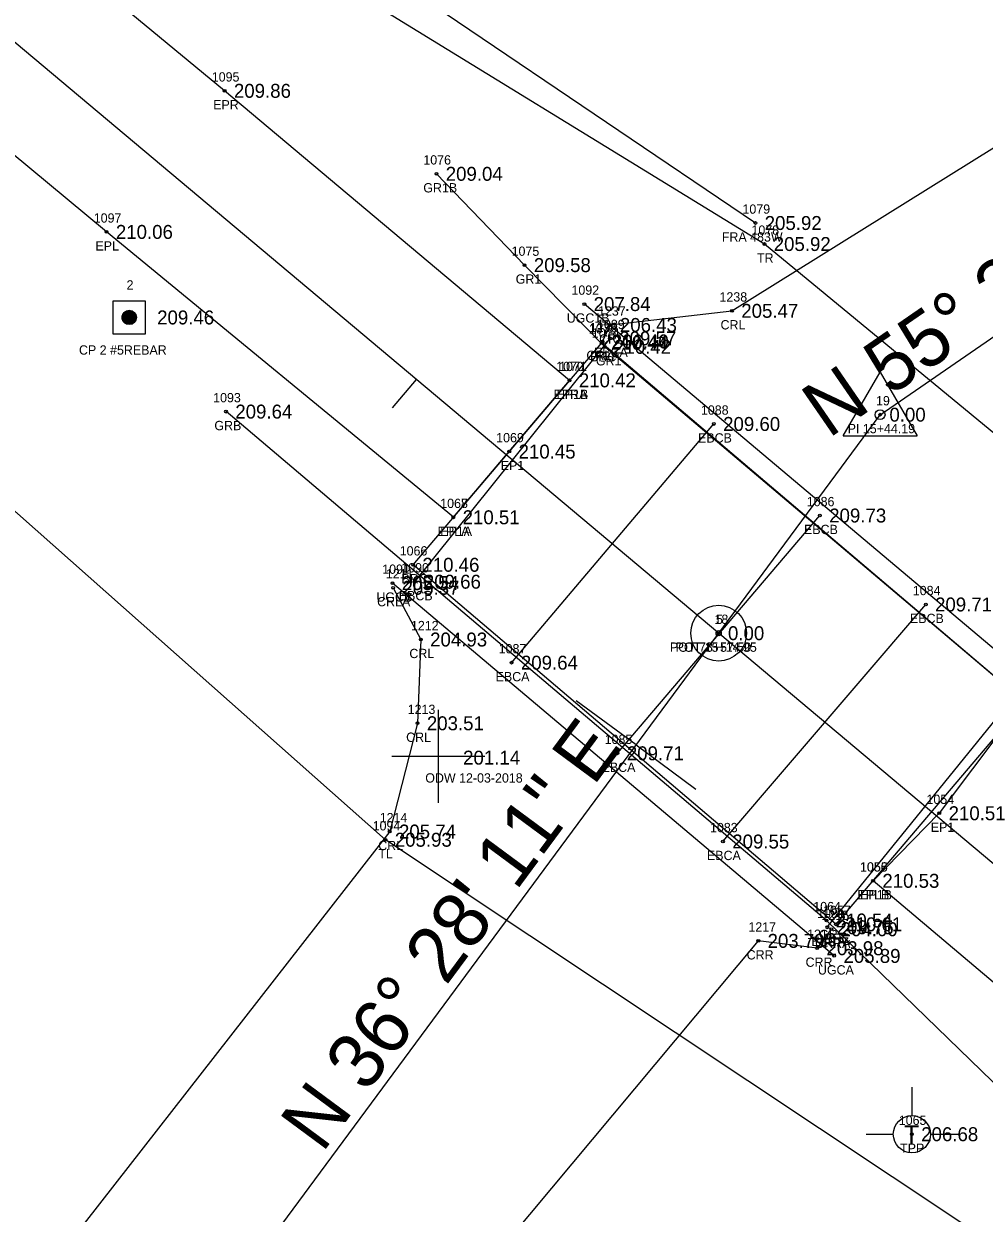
# Model space of a CAD drawing. Extents: x 2259948 to 2261336, y 1064647 to 1065986.
# Drawn here: x 2260727.2 to 2260830.6, y 1065022.5 to 1065150.5 of the extents above; entities that cross this region are included whole.
import ezdxf

# ---------------------------------------------------------------- set-up
doc = ezdxf.new("R2010")
doc.units = 0
for name, color, linetype in [('RD_EX_Bridge', 7, 'Continuous'), ('RD_EX_Bridge_txCode', 7, 'Continuous'), ('RD_EX_Fence_Other', 7, 'Continuous'), ('RD_EX_Fence_Other_txCode', 7, 'Continuous'), ('RD_EX_GuardRail', 7, 'Continuous'), ('RD_EX_GuardRail_txCode', 7, 'Continuous'), ('RD_EX_H2O', 7, 'Continuous'), ('RD_EX_H2O_txCode', 7, 'Continuous'), ('RD_EX_Road', 7, 'Continuous'), ('RD_EX_Road_txCode', 7, 'Continuous'), ('RD_EX_TX_Bridge_ELEV', 7, 'Continuous'), ('RD_EX_TX_Fence_Other_ELEV', 7, 'Continuous'), ('RD_EX_TX_GuardRail_ELEV', 7, 'Continuous'), ('RD_EX_TX_H2O_ELEV', 7, 'Continuous'), ('RD_EX_TX_Road_ELEV', 7, 'Continuous'), ('RD_EX_TX_UT_ELEV', 7, 'Continuous'), ('RD_EX_TX_VEG_ELEV', 7, 'Continuous'), ('RD_EX_UT', 7, 'Continuous'), ('RD_EX_UT_txCode', 7, 'Continuous'), ('RD_EX_VEG', 7, 'Continuous'), ('RD_EX_VEG_txCode', 7, 'Continuous'), ('RD_HC_Cl', 7, 'Continuous'), ('RD_HC_Data', 7, 'Continuous'), ('RD_HC_Data_Tic', 7, 'Continuous'), ('RD_HC_Survey', 7, 'Continuous'), ('RD_HC_Survey_ELEV', 7, 'Continuous'), ('RD_HC_Survey_txCode', 7, 'Continuous'), ('RD_HC_txCode', 7, 'Continuous'), ('RD_SMD_Locator', 7, 'Continuous')]:
    doc.layers.add(name, color=color, linetype=linetype)

msp = doc.modelspace()

# ---------------------------------------------------------------- linework, layer by layer
at = {"layer": 'RD_EX_Bridge'}
for p, q in [((2260790.29, 1065116.62), (2260769.27, 1065090.44)), ((2260779.71, 1065081.73), (2260801.47, 1065107.41)), ((2260791.11, 1065071.98), (2260812.88, 1065097.56)), ((2260802.45, 1065062.49), (2260824.27, 1065087.99)), ((2260813.68, 1065053.26), (2260834.73, 1065079.24))]:
    msp.add_line(p, q, dxfattribs=at)
msp.add_lwpolyline([(2260834.92, 1065077.53), (2260814.6, 1065053.58), (2260769.11, 1065092.26), (2260789.4, 1065116.14), (2260834.92, 1065077.53)], dxfattribs=at)
at = {"layer": 'RD_EX_Fence_Other'}
msp.add_lwpolyline([(2260805.94, 1065129.03), (2260757.87, 1065161.54), (2260648.62, 1065258.75)], dxfattribs=at)
at = {"layer": 'RD_EX_GuardRail'}
for points in [[(2260856.34, 1065064.4), (2260844.56, 1065071.16), (2260834.49, 1065077.85), (2260789.73, 1065115.71), (2260781.1, 1065124.5), (2260771.62, 1065134.32)], [(2260832.64, 1065035.52), (2260813.58, 1065053.99), (2260748.98, 1065108.74)]]:
    msp.add_lwpolyline(points, dxfattribs=at)
at = {"layer": 'RD_EX_H2O'}
for p, q in [((2260771.83, 1065066.66), (2260771.83, 1065076.66)), ((2260766.83, 1065071.66), (2260776.83, 1065071.66))]:
    msp.add_line(p, q, dxfattribs=at)
for points in [[(2260789.48, 1065116.29), (2260790.36, 1065118.06), (2260803.42, 1065119.58), (2260845.64, 1065145.91), (2260874.83, 1065172.21)], [(2260766.96, 1065089.79), (2260769.94, 1065084.22), (2260769.59, 1065075.21), (2260766.59, 1065063.56), (2260718.2, 1065001.51), (2260666.03, 1064928.94), (2260617.31, 1064851.47), (2260573.34, 1064761.94), (2260536.11, 1064718.88), (2260488.15, 1064682.39)], [(2260814.11, 1065053.05), (2260812.59, 1065051.01), (2260806.25, 1065051.8), (2260750.48, 1064985.06), (2260697.06, 1064907.27), (2260648.8, 1064826.07), (2260606.38, 1064743.85), (2260584.89, 1064714.82), (2260586.34, 1064702.25), (2260547.45, 1064661.75), (2260541.67, 1064664.24), (2260523.34, 1064649.3)]]:
    msp.add_lwpolyline(points, dxfattribs=at)
at = {"layer": 'RD_EX_Road'}
for points in [[(2260785.94, 1065112.1), (2260748.83, 1065143.25), (2260679.89, 1065200.15), (2260614.93, 1065253.84), (2260576.4, 1065286.6), (2260541.88, 1065316.4), (2260503.82, 1065350.69)], [(2260773.44, 1065097.37), (2260736.13, 1065128.07), (2260602.8, 1065238.77), (2260563.77, 1065270.54), (2260528.16, 1065301.97), (2260490.72, 1065336.18)], [(2260773.44, 1065097.37), (2260779.46, 1065104.44), (2260785.94, 1065112.1)], [(2260832.89, 1065075.07), (2260825.73, 1065065.53), (2260818.6, 1065058.26)], [(2261112.68, 1064810.86), (2261032.95, 1064877.72), (2260956.01, 1064942.53), (2260884.53, 1065002.6), (2260818.6, 1065058.26)]]:
    msp.add_lwpolyline(points, dxfattribs=at)
at = {"layer": 'RD_EX_UT'}
for p, q in [((2260837.52, 1065078.2), (2260787.54, 1065120.31)), ((2260814.42, 1065050.18), (2260766.89, 1065090.29)), ((2260822.78, 1065036.07), (2260822.78, 1065033)), ((2260817.85, 1065031.01), (2260820.78, 1065031.01)), ((2260824.78, 1065031.01), (2260827.85, 1065031.01))]:
    msp.add_line(p, q, dxfattribs=at)
msp.add_circle((2260822.78, 1065031), 2, dxfattribs=at)
at = {"layer": 'RD_EX_VEG'}
for points in [[(2261134.31, 1064842.95), (2260842.2, 1065097.67), (2260806.91, 1065126.77), (2260758.4, 1065156.57), (2260401.57, 1065481.47), (2260414.95, 1065532.7)], [(2261105.29, 1064796.67), (2260883, 1064984.96), (2260766.14, 1065062.68), (2260367.33, 1065416.28), (2260257.33, 1065527.76)]]:
    msp.add_lwpolyline(points, dxfattribs=at)
at = {"layer": 'RD_HC_Cl'}
for p, q in [((2261118.79, 1064819.11), (2260589.55, 1065263.13)), ((2260819.36, 1065108.41), (2260855.45, 1065133.27)), ((2260734.19, 1064993.17), (2260819.36, 1065108.41))]:
    msp.add_line(p, q, dxfattribs=at)
at = {"layer": 'RD_HC_Data'}
for p, q in [((2260815.39, 1065106.12), (2260819.37, 1065113)), ((2260819.37, 1065113), (2260823.33, 1065106.12)), ((2260815.39, 1065106.12), (2260823.33, 1065106.12))]:
    msp.add_line(p, q, dxfattribs=at)
for centre, radius in [((2260819.36, 1065108.41), 0.529), ((2260801.99, 1065084.9), 3), ((2260801.99, 1065084.9), 3), ((2260801.99, 1065084.9), 0.282), ((2260801.99, 1065084.9), 0.282)]:
    msp.add_circle(centre, radius, dxfattribs=at)
at = {"layer": 'RD_HC_Data_Tic'}
for p, q in [((2260769.43, 1065112.21), (2260766.86, 1065109.15)), ((2260793.1, 1065072.88), (2260786.67, 1065077.63)), ((2260793.1, 1065072.88), (2260799.53, 1065068.12))]:
    msp.add_line(p, q, dxfattribs=at)
at = {"layer": 'RD_HC_Survey'}
for p, q in [((2260737.84, 1065118.6), (2260737.84, 1065119.13)), ((2260737.87, 1065118.54), (2260737.87, 1065119.19)), ((2260737.89, 1065118.49), (2260737.89, 1065119.24)), ((2260737.92, 1065118.45), (2260737.92, 1065119.28)), ((2260737.94, 1065118.42), (2260737.94, 1065119.31)), ((2260737.97, 1065118.38), (2260737.97, 1065119.35)), ((2260737.99, 1065118.35), (2260737.99, 1065119.38)), ((2260738.02, 1065118.33), (2260738.02, 1065119.4)), ((2260738.04, 1065118.3), (2260738.04, 1065119.43)), ((2260738.07, 1065118.28), (2260738.07, 1065119.45)), ((2260738.09, 1065118.26), (2260738.09, 1065119.47)), ((2260738.11, 1065118.24), (2260738.11, 1065119.49)), ((2260738.14, 1065118.22), (2260738.14, 1065119.51)), ((2260738.16, 1065118.21), (2260738.16, 1065119.52)), ((2260738.19, 1065118.19), (2260738.19, 1065119.54)), ((2260738.21, 1065118.18), (2260738.21, 1065119.55)), ((2260738.24, 1065118.17), (2260738.24, 1065119.56)), ((2260738.26, 1065118.16), (2260738.26, 1065119.57)), ((2260738.29, 1065118.15), (2260738.29, 1065119.58)), ((2260738.31, 1065118.14), (2260738.31, 1065119.59)), ((2260738.34, 1065118.13), (2260738.34, 1065119.6)), ((2260738.36, 1065118.12), (2260738.36, 1065119.61)), ((2260738.39, 1065118.12), (2260738.39, 1065119.61)), ((2260738.41, 1065118.11), (2260738.41, 1065119.62)), ((2260738.44, 1065118.11), (2260738.44, 1065119.62)), ((2260738.46, 1065118.1), (2260738.46, 1065119.63)), ((2260738.49, 1065118.1), (2260738.49, 1065119.63)), ((2260738.51, 1065118.1), (2260738.51, 1065119.63)), ((2260738.54, 1065118.1), (2260738.54, 1065119.63)), ((2260738.56, 1065118.1), (2260738.56, 1065119.63)), ((2260738.59, 1065118.1), (2260738.59, 1065119.63)), ((2260738.61, 1065118.1), (2260738.61, 1065119.63)), ((2260738.63, 1065118.1), (2260738.63, 1065119.63)), ((2260738.66, 1065118.1), (2260738.66, 1065119.63)), ((2260738.68, 1065118.1), (2260738.68, 1065119.63)), ((2260738.71, 1065118.11), (2260738.71, 1065119.62)), ((2260738.73, 1065118.11), (2260738.73, 1065119.62)), ((2260738.76, 1065118.12), (2260738.76, 1065119.61)), ((2260738.78, 1065118.13), (2260738.78, 1065119.6)), ((2260738.81, 1065118.13), (2260738.81, 1065119.6)), ((2260738.83, 1065118.14), (2260738.83, 1065119.59)), ((2260738.86, 1065118.15), (2260738.86, 1065119.58)), ((2260738.88, 1065118.16), (2260738.88, 1065119.57)), ((2260738.91, 1065118.18), (2260738.91, 1065119.56)), ((2260738.93, 1065118.19), (2260738.93, 1065119.54)), ((2260738.96, 1065118.2), (2260738.96, 1065119.53)), ((2260738.98, 1065118.22), (2260738.98, 1065119.51)), ((2260739.01, 1065118.23), (2260739.01, 1065119.5)), ((2260739.03, 1065118.25), (2260739.03, 1065119.48)), ((2260739.06, 1065118.27), (2260739.06, 1065119.46)), ((2260739.08, 1065118.29), (2260739.08, 1065119.44)), ((2260739.1, 1065118.32), (2260739.1, 1065119.41)), ((2260739.13, 1065118.34), (2260739.13, 1065119.39)), ((2260739.15, 1065118.37), (2260739.15, 1065119.36)), ((2260739.18, 1065118.4), (2260739.18, 1065119.33)), ((2260739.2, 1065118.43), (2260739.2, 1065119.3)), ((2260739.23, 1065118.47), (2260739.23, 1065119.26)), ((2260739.25, 1065118.52), (2260739.25, 1065119.21)), ((2260739.28, 1065118.57), (2260739.28, 1065119.16)), ((2260739.3, 1065118.64), (2260739.3, 1065119.09)), ((2260737.82, 1065118.69), (2260737.82, 1065119.04)), ((2260739.33, 1065118.75), (2260739.33, 1065118.98))]:
    msp.add_line(p, q, dxfattribs=at)
msp.add_lwpolyline([(2260740.32, 1065120.62), (2260736.82, 1065120.62), (2260736.82, 1065117.12), (2260740.32, 1065117.12)], close=True, dxfattribs=at)
msp.add_circle((2260738.57, 1065118.87), 0.769, dxfattribs=at)
at = {"layer": 'RD_SMD_Locator'}
for centre in [(2260748.83, 1065143.25), (2260771.62, 1065134.32), (2260736.13, 1065128.07), (2260805.94, 1065129.03), (2260806.91, 1065126.77), (2260781.1, 1065124.5), (2260787.54, 1065120.31), (2260803.42, 1065119.58), (2260738.57, 1065118.87), (2260790.36, 1065118.06), (2260790.29, 1065116.62), (2260789.4, 1065116.14), (2260789.48, 1065116.29), (2260789.73, 1065115.71), (2260785.94, 1065112.1), (2260785.94, 1065112.1), (2260748.98, 1065108.74), (2260801.47, 1065107.41), (2260819.36, 1065108.41), (2260779.46, 1065104.44), (2260773.44, 1065097.37), (2260773.44, 1065097.37), (2260812.88, 1065097.56), (2260769.11, 1065092.26), (2260766.89, 1065090.29), (2260766.96, 1065089.79), (2260769.27, 1065090.44), (2260824.27, 1065087.99), (2260801.99, 1065084.9), (2260801.99, 1065084.9), (2260769.94, 1065084.22), (2260779.71, 1065081.73), (2260769.59, 1065075.21), (2260791.11, 1065071.98), (2260825.73, 1065065.53), (2260766.14, 1065062.68), (2260766.59, 1065063.56), (2260802.45, 1065062.49), (2260818.6, 1065058.26), (2260818.6, 1065058.26), (2260813.58, 1065053.99), (2260813.68, 1065053.26), (2260814.11, 1065053.05), (2260814.6, 1065053.58), (2260806.25, 1065051.8), (2260812.59, 1065051.01), (2260814.42, 1065050.18), (2260822.78, 1065031)]:
    msp.add_circle(centre, 0.15, dxfattribs=at)

# ---------------------------------------------------------------- texts
at = {"layer": 'RD_EX_Bridge_txCode'}
for s, p in [('1072', (2260788.02, 1065117.14)), ('1089', (2260788.9, 1065117.62)), ('EBCA', (2260788.57, 1065114.62)), ('BRC', (2260788.15, 1065114.14)), ('1088', (2260800.08, 1065108.41)), ('EBCB', (2260799.77, 1065105.41)), ('1086', (2260811.47, 1065098.56)), ('EBCB', (2260811.17, 1065095.56)), ('1066', (2260767.67, 1065093.26)), ('1090', (2260767.84, 1065091.44)), ('BRC', (2260767.86, 1065090.26)), ('1084', (2260822.88, 1065088.99)), ('EBCB', (2260767.57, 1065088.44)), ('EBCB', (2260822.57, 1065085.99)), ('1087', (2260778.32, 1065082.73)), ('EBCA', (2260777.99, 1065079.73)), ('1085', (2260789.72, 1065072.98)), ('EBCA', (2260789.39, 1065069.98)), ('1083', (2260801.06, 1065063.49)), ('EBCA', (2260800.73, 1065060.49)), ('1081', (2260812.58, 1065054.26)), ('1057', (2260813.22, 1065054.58)), ('BRC', (2260813.35, 1065051.58)), ('EBCA', (2260811.96, 1065051.26))]:
    msp.add_text(s, height=1, dxfattribs=at).set_placement(p)
at = {"layer": 'RD_EX_Fence_Other_txCode'}
for s, p in [('1079', (2260804.55, 1065130.03)), ('FRA 483W', (2260802.33, 1065127.03))]:
    msp.add_text(s, height=1, dxfattribs=at).set_placement(p)
at = {"layer": 'RD_EX_GuardRail_txCode'}
for s, p in [('1076', (2260770.21, 1065135.32)), ('GR1B', (2260770.21, 1065132.32)), ('1075', (2260779.71, 1065125.5)), ('GR1', (2260780.15, 1065122.5)), ('1074', (2260788.34, 1065116.71)), ('GR1', (2260788.78, 1065113.71)), ('1093', (2260747.6, 1065109.74)), ('GRB', (2260747.73, 1065106.74)), ('1064', (2260812.17, 1065054.99)), ('GR', (2260812.8, 1065051.99))]:
    msp.add_text(s, height=1, dxfattribs=at).set_placement(p)
at = {"layer": 'RD_EX_H2O_txCode'}
for s, p in [('1238', (2260802.08, 1065120.58)), ('1237', (2260789.01, 1065119.06)), ('1236', (2260788.11, 1065117.29)), ('CRL', (2260802.19, 1065117.58)), ('CRL', (2260789.13, 1065116.06)), ('CRLA', (2260787.76, 1065114.29)), ('1211', (2260766.18, 1065090.79)), ('CRLA', (2260765.24, 1065087.79)), ('1212', (2260768.88, 1065085.22)), ('CRL', (2260768.71, 1065082.22)), ('1213', (2260768.53, 1065076.21)), ('CRL', (2260768.36, 1065073.21)), ('ODW 12-03-2018', (2260770.42, 1065068.83)), ('1214', (2260765.52, 1065064.56)), ('CRL', (2260765.36, 1065061.56)), ('1217', (2260805.19, 1065052.8)), ('1215', (2260813.05, 1065054.05)), ('1216', (2260811.5, 1065052.01)), ('CRRA', (2260812.37, 1065051.05)), ('CRR', (2260805, 1065049.8)), ('CRR', (2260811.34, 1065049.01))]:
    msp.add_text(s, height=1, dxfattribs=at).set_placement(p)
at = {"layer": 'RD_EX_Road_txCode'}
for s, p in [('1095', (2260747.45, 1065144.25)), ('EPR', (2260747.6, 1065141.25)), ('1097', (2260734.75, 1065129.07)), ('EPL', (2260734.93, 1065126.07)), ('1070', (2260784.51, 1065113.1)), ('1071', (2260784.83, 1065113.1)), ('EPRA', (2260784.22, 1065110.1)), ('EP1B', (2260784.54, 1065110.1)), ('1069', (2260778.05, 1065105.44)), ('EP1', (2260778.54, 1065102.44)), ('1067', (2260772.03, 1065098.37)), ('1068', (2260772.03, 1065098.37)), ('EPLA', (2260771.75, 1065095.37)), ('EP1A', (2260772.03, 1065095.37)), ('1054', (2260824.35, 1065066.53)), ('EP1', (2260824.81, 1065063.53)), ('1056', (2260817.19, 1065059.26)), ('1055', (2260817.21, 1065059.26)), ('EPLB', (2260816.92, 1065056.26)), ('EP1B', (2260817.21, 1065056.26))]:
    msp.add_text(s, height=1, dxfattribs=at).set_placement(p)
at = {"layer": 'RD_EX_TX_Bridge_ELEV'}
for s, p in [('210.44', (2260790.4, 1065115.39)), ('209.57', (2260791.29, 1065115.87)), ('209.60', (2260802.47, 1065106.66)), ('209.73', (2260813.88, 1065096.81)), ('210.46', (2260770.11, 1065091.51)), ('209.66', (2260770.27, 1065089.69)), ('209.71', (2260825.27, 1065087.24)), ('209.64', (2260780.71, 1065080.98)), ('209.71', (2260792.11, 1065071.23)), ('209.55', (2260803.45, 1065061.74)), ('209.75', (2260814.68, 1065052.51)), ('210.61', (2260815.6, 1065052.83))]:
    msp.add_text(s, height=1.5, dxfattribs=at).set_placement(p)
at = {"layer": 'RD_EX_TX_Fence_Other_ELEV'}
msp.add_text('205.92', height=1.5, dxfattribs=at).set_placement((2260806.94, 1065128.28))
at = {"layer": 'RD_EX_TX_GuardRail_ELEV'}
for s, p in [('209.04', (2260772.62, 1065133.57)), ('209.58', (2260782.1, 1065123.75)), ('210.42', (2260790.73, 1065114.96)), ('209.64', (2260749.98, 1065107.99)), ('210.54', (2260814.58, 1065053.24))]:
    msp.add_text(s, height=1.5, dxfattribs=at).set_placement(p)
at = {"layer": 'RD_EX_TX_H2O_ELEV'}
for s, p in [('205.47', (2260804.42, 1065118.83)), ('206.43', (2260791.36, 1065117.31)), ('206.40', (2260790.48, 1065115.54)), ('205.37', (2260767.96, 1065089.04)), ('204.93', (2260770.94, 1065083.47)), ('203.51', (2260770.59, 1065074.46)), ('201.14', (2260774.49, 1065070.76)), ('205.74', (2260767.59, 1065062.81)), ('204.00', (2260815.11, 1065052.3)), ('203.79', (2260807.25, 1065051.05)), ('203.98', (2260813.59, 1065050.26))]:
    msp.add_text(s, height=1.5, dxfattribs=at).set_placement(p)
at = {"layer": 'RD_EX_TX_Road_ELEV'}
for s, p in [('209.86', (2260749.83, 1065142.5)), ('210.06', (2260737.13, 1065127.32)), ('210.42', (2260786.94, 1065111.35)), ('210.42', (2260786.94, 1065111.35)), ('210.45', (2260780.46, 1065103.69)), ('210.51', (2260774.44, 1065096.62)), ('210.51', (2260774.44, 1065096.62)), ('210.51', (2260826.73, 1065064.78)), ('210.53', (2260819.6, 1065057.51)), ('210.53', (2260819.6, 1065057.51))]:
    msp.add_text(s, height=1.5, dxfattribs=at).set_placement(p)
at = {"layer": 'RD_EX_TX_UT_ELEV'}
for s, p in [('207.84', (2260788.54, 1065119.56)), ('205.54', (2260767.89, 1065089.54)), ('205.89', (2260815.42, 1065049.43)), ('206.68', (2260823.78, 1065030.25))]:
    msp.add_text(s, height=1.5, dxfattribs=at).set_placement(p)
at = {"layer": 'RD_EX_TX_VEG_ELEV'}
for s, p in [('205.92', (2260807.91, 1065126.02)), ('205.93', (2260767.14, 1065061.93))]:
    msp.add_text(s, height=1.5, dxfattribs=at).set_placement(p)
at = {"layer": 'RD_EX_UT'}
msp.add_text('T', height=2, dxfattribs=at).set_placement((2260821.93, 1065029.95))
at = {"layer": 'RD_EX_UT_txCode'}
for s, p in [('1092', (2260786.15, 1065121.31)), ('UGC1B', (2260785.64, 1065118.31)), ('1091', (2260765.79, 1065091.29)), ('UGCB', (2260765.16, 1065088.29)), ('1077', (2260813.03, 1065051.18)), ('UGCA', (2260812.67, 1065048.18)), ('1065', (2260821.37, 1065032)), ('TPP', (2260821.51, 1065029))]:
    msp.add_text(s, height=1, dxfattribs=at).set_placement(p)
at = {"layer": 'RD_EX_VEG_txCode'}
for s, p in [('1078', (2260805.52, 1065127.77)), ('TR', (2260806.11, 1065124.77)), ('1094', (2260764.76, 1065063.68)), ('TL', (2260765.37, 1065060.68))]:
    msp.add_text(s, height=1, dxfattribs=at).set_placement(p)
at = {"layer": 'RD_HC_Data'}
for s, rotation, p in [('N 55%%d 26\' 21" E', 34.5607, (2260813.8, 1065105.79)), ('N 36%%d 28\' 11" E', 53.5303, (2260759.34, 1065028.89))]:
    msp.add_text(s, height=6, rotation=rotation, dxfattribs=at).set_placement(p)
at = {"layer": 'RD_HC_Survey_ELEV'}
for s, p in [('209.46', (2260741.57, 1065118.12)), ('0.00', (2260820.36, 1065107.66)), ('0.00', (2260802.99, 1065084.15)), ('0.00', (2260802.99, 1065084.15))]:
    msp.add_text(s, height=1.5, dxfattribs=at).set_placement(p)
at = {"layer": 'RD_HC_Survey_txCode'}
for s, p in [('2', (2260738.28, 1065121.87)), ('CP 2 #5REBAR', (2260733.16, 1065114.87))]:
    msp.add_text(s, height=1, dxfattribs=at).set_placement(p)
at = {"layer": 'RD_HC_txCode'}
for s, p in [('19', (2260818.92, 1065109.41)), ('PI 15+44.19', (2260815.87, 1065106.41)), ('18', (2260801.54, 1065085.9)), ('5', (2260801.7, 1065085.9)), ('POT 78+57.50', (2260796.75, 1065082.9)), ('POT 15+14.95', (2260797.36, 1065082.9))]:
    msp.add_text(s, height=1, dxfattribs=at).set_placement(p)

doc.saveas('drawing.dxf')
